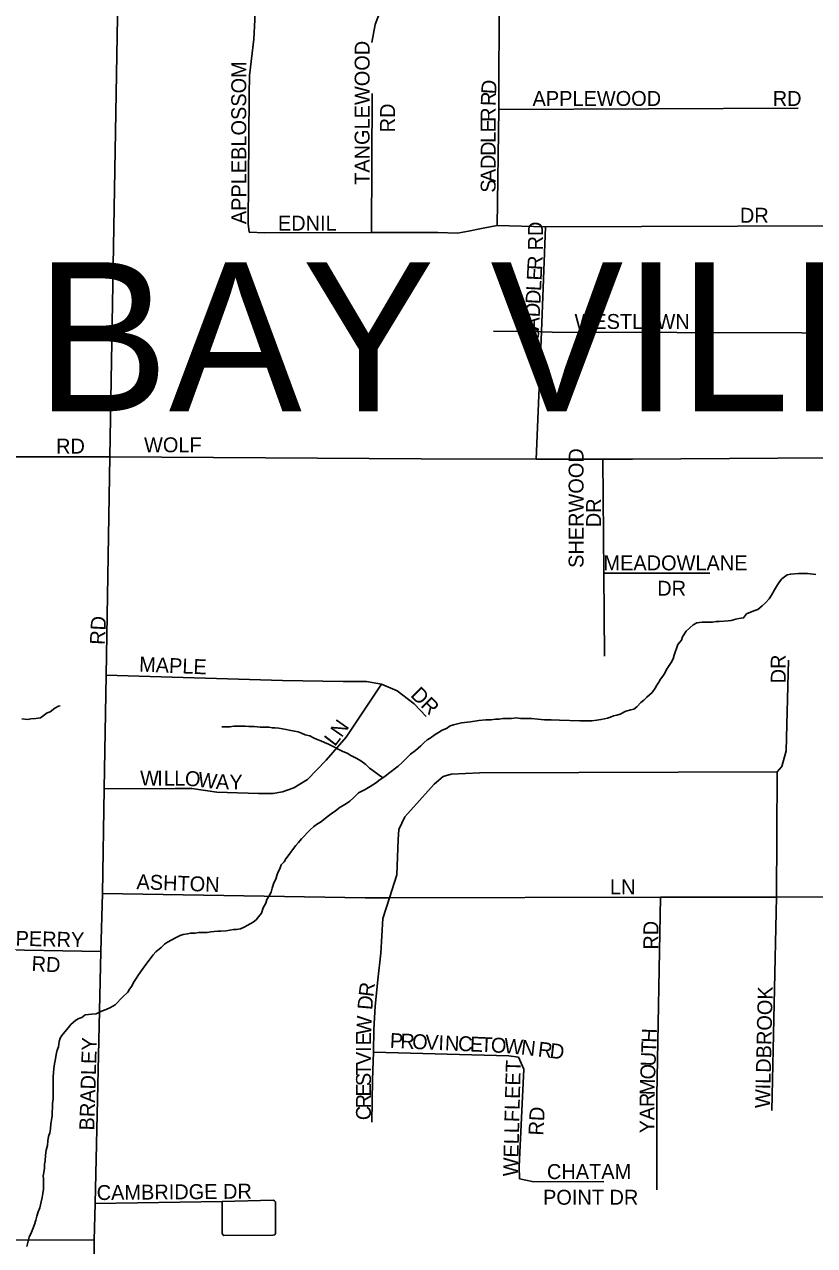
# Model space of a CAD drawing. Extents: x 2010165 to 2382125, y 1060529 to 1407316.
# Drawn here: x 2116231 to 2118880, y 1267507 to 1271602 of the extents above; entities that cross this region are included whole.
import ezdxf

# ---------------------------------------------------------------- set-up
doc = ezdxf.new("R2010")
doc.units = 0
for name, color, linetype in [('GM_X_City_Street', 7, 'Continuous'), ('GM_X_City_Street_Text', 7, 'Continuous'), ('GM_X_Corporation_Text', 7, 'Continuous'), ('GM_X_Minor_River', 7, 'Continuous')]:
    doc.layers.add(name, color=color, linetype=linetype)

msp = doc.modelspace()

# ---------------------------------------------------------------- linework, layer by layer
at = {"layer": 'GM_X_City_Street'}
for points in [[(2116464.5, 1267467), (2116465.1, 1267525), (2116467.9, 1267647.2), (2116487.6, 1268493.4), (2116492.2, 1268687.3), (2116498.1, 1269038.7), (2116504.5, 1269419.7), (2116516.9, 1270152.2), (2116550.8, 1272077), (2116556.8, 1272422.1), (2116559, 1272542.9), (2116566.7, 1272843.5), (2116570.2, 1273148.5), (2116574.6, 1273527.5), (2116584.4, 1274380.4), (2116589.8, 1274845.8)], [(2116984.6, 1270905.5), (2116980.7, 1270933.5), (2116984.7, 1271366.6), (2116985, 1271430.7), (2116999.5, 1271553), (2117003.8, 1271617.1), (2117007.3, 1271755.5), (2117011.2, 1271907.8), (2117013.4, 1271949.9), (2117023.5, 1271985.9), (2117043.7, 1272025.9), (2117070.1, 1272100), (2117090.3, 1272146), (2117097.6, 1272173.4), (2117110.7, 1272222.1), (2117125, 1272294.2), (2117135.6, 1272412.5), (2117147.1, 1272741.3)], [(2117395.9, 1271541.3), (2117406.2, 1271601.4), (2117436.5, 1271681.5), (2117453.8, 1271719), (2117499.2, 1271817.6), (2117531.6, 1271897.6), (2117554.1, 1271989.7), (2117557.2, 1272021.7), (2117581.4, 1272272.3), (2117603.6, 1272739.6)], [(2117815.5, 1270928.1), (2117821, 1271317.1), (2117821.4, 1271347.1), (2117822.9, 1271679.9)], [(2117394.9, 1270904.2), (2117397.1, 1271370.9)], [(2117821, 1271317.1), (2118824.3, 1271320.9)], [(2116984.6, 1270905.5), (2117036.6, 1270903.2), (2117394.9, 1270904.2), (2117617.2, 1270904.9), (2117683.2, 1270902.6), (2117719.3, 1270908.4), (2117763.4, 1270918.3), (2117815.5, 1270928.1), (2117977.6, 1270923.4), (2119264.7, 1270928)], [(2117946.1, 1270144.6), (2117963.9, 1270571), (2117964, 1270572.6), (2117977.6, 1270923.4)], [(2117803.9, 1270573.3), (2117963.9, 1270571), (2118000.1, 1270570.5), (2119255.1, 1270567.1)], [(2116516.9, 1270152.2), (2117561.4, 1270145.3), (2117946.1, 1270144.6), (2118170.3, 1270144.2), (2118269.7, 1270144.1), (2119244.1, 1270151.1), (2119848.3, 1270161.8), (2120170.4, 1270158.2), (2120248.4, 1270170.3), (2120330.4, 1270228.5), (2120476.4, 1270308.7), (2120580.4, 1270361), (2120672.5, 1270395.1), (2120792, 1270390.5), (2120970.6, 1270369.4)], [(2115138.1, 1270150.7), (2115580.8, 1270151.2), (2116011.9, 1270151.6), (2116516.9, 1270152.2)], [(2118175.3, 1269483.1), (2118173.2, 1269761.7), (2118170.3, 1270144.2)], [(2118173.2, 1269761.7), (2118528.9, 1269762.3)], [(2118736.9, 1267959.1), (2118752.2, 1268675.7), (2118754.1, 1269095.8), (2118770.2, 1269113.8), (2118784.4, 1269165.8), (2118791.9, 1269470.5)], [(2116498.1, 1269038.7), (2116735.8, 1269039.9), (2116791.9, 1269039.7), (2116875.9, 1269027.3), (2117016, 1269022.8), (2117064.1, 1269022.5), (2117096.2, 1269028.4), (2117134.2, 1269042.3), (2117180.4, 1269070.2), (2117242.8, 1269134.1), (2117309.2, 1269212), (2117428.1, 1269389.9)], [(2116504.5, 1269419.7), (2117095.8, 1269401.3), (2117300, 1269398.5), (2117378.1, 1269398.2), (2117428.1, 1269389.9), (2117480.1, 1269367.7), (2117537.9, 1269323.3), (2117577.8, 1269281.1)], [(2117395.4, 1267920.5), (2117398.1, 1268062.9), (2117400.7, 1268155.2), (2117402.8, 1268231.2), (2117407.2, 1268309.4), (2117415.6, 1268397.6), (2117426, 1268487.8), (2117432.5, 1268604), (2117454.5, 1268672.6), (2117479.3, 1268750.2), (2117483.8, 1268868.4), (2117486, 1268902.5), (2117506.2, 1268944.5), (2117604.8, 1269054.4), (2117634.9, 1269080.3), (2117661, 1269088.2), (2117757.1, 1269091.9), (2118754.1, 1269095.8)], [(2116492.2, 1268687.3), (2117372.8, 1268672.4), (2117454.5, 1268672.6), (2118363.7, 1268674.8), (2118752.2, 1268675.7), (2119215.2, 1268676.8)], [(2118351.3, 1267694), (2118350.8, 1268008.8), (2118363.7, 1268674.8)], [(2116102.8, 1268499.2), (2116487.6, 1268493.4)], [(2117400.7, 1268155.2), (2117854.9, 1268143.2), (2117886.9, 1268139)], [(2117891, 1267730), (2117889.2, 1267772.1), (2117904.7, 1268098.8), (2117886.9, 1268139)], [(2117891, 1267730), (2117933, 1267721.8), (2118173.3, 1267720.8)], [(2116467.9, 1267647.2), (2116894, 1267654.4)], [(2116894, 1267654.4), (2116894, 1267547.7), (2116896.5, 1267542.7), (2116899.9, 1267540.1), (2117064.2, 1267541.7), (2117069.9, 1267543.2), (2117072.4, 1267547.6), (2117072.1, 1267652.9), (2117069.6, 1267657), (2117064.9, 1267658.8), (2116894, 1267654.4)], [(2113971.4, 1267533.5), (2116465.1, 1267525)]]:
    msp.add_lwpolyline(points, dxfattribs=at)
at = {"layer": 'GM_X_Minor_River'}
for points in [[(2117796.1, 1269269.8), (2117810.1, 1269271.8), (2117822.2, 1269271.9), (2117834.2, 1269273.9), (2117848.2, 1269273.9), (2117864.3, 1269274), (2117880.3, 1269276.1), (2117894.4, 1269274.1), (2117912.5, 1269274.2), (2117930.5, 1269274.2), (2117952.6, 1269272.3), (2117974.7, 1269270.3), (2117996.8, 1269270.4), (2118024.9, 1269268.5), (2118093.1, 1269266.7), (2118113.2, 1269266.8), (2118133.2, 1269266.8), (2118149.3, 1269268.9), (2118163.3, 1269270.9), (2118175.3, 1269273), (2118185.4, 1269275), (2118195.4, 1269279.1), (2118205.4, 1269283.1), (2118217.4, 1269285.2), (2118227.5, 1269289.2), (2118247.5, 1269299.3), (2118263.5, 1269303.4), (2118273.6, 1269305.4), (2118283.6, 1269313.5), (2118297.6, 1269327.6), (2118307.6, 1269335.6), (2118317.6, 1269345.7), (2118335.6, 1269361.8), (2118345.6, 1269375.9), (2118351.5, 1269385.9), (2118357.5, 1269396), (2118363.5, 1269406), (2118371.5, 1269416.1), (2118377.5, 1269426.1), (2118383.5, 1269438.2), (2118399.4, 1269462.3), (2118405.4, 1269474.4), (2118409.4, 1269486.4), (2118421.3, 1269522.6), (2118433.3, 1269536.7), (2118437.3, 1269548.7), (2118449.2, 1269566.8), (2118473.2, 1269589), (2118485.3, 1269595), (2118503.3, 1269597.1), (2118525.4, 1269597.2), (2118537.4, 1269597.2), (2118549.5, 1269599.2), (2118559.5, 1269599.3), (2118589.6, 1269601.4), (2118599.6, 1269603.4), (2118615.7, 1269607.5), (2118625.7, 1269609.5), (2118641.7, 1269611.6), (2118651.7, 1269625.7), (2118675.8, 1269635.8), (2118689.8, 1269639.8), (2118703.8, 1269651.9), (2118715.8, 1269662), (2118727.8, 1269676.1), (2118735.8, 1269688.1), (2118745.8, 1269706.2), (2118755.7, 1269722.3), (2118761.7, 1269732.3), (2118769.7, 1269742.4), (2118787.7, 1269756.5), (2118799.8, 1269758.6), (2118825.8, 1269760.6), (2118843.9, 1269760.7), (2118855.9, 1269760.8), (2118884, 1269756.8)], [(2116222.8, 1269272.8), (2116240.9, 1269270.8), (2116252.9, 1269272.9), (2116268.9, 1269274.9), (2116285, 1269277), (2116307, 1269293.1), (2116317, 1269297.2), (2116333, 1269309.2), (2116345.1, 1269315.3), (2116351.1, 1269317.3)], [(2116519.1, 1268304.6), (2116535.2, 1268314.6), (2116561.2, 1268340.8), (2116577.1, 1268356.9), (2116583.1, 1268367), (2116591.1, 1268377), (2116597.1, 1268389.1), (2116603.1, 1268399.1), (2116613.1, 1268415.2), (2116627, 1268433.3), (2116641, 1268453.4), (2116649, 1268463.5), (2116663, 1268481.6), (2116671, 1268491.6), (2116689, 1268505.8), (2116701, 1268517.8), (2116711, 1268523.9), (2116725, 1268532), (2116739.1, 1268540), (2116753.1, 1268546.1), (2116763.1, 1268550.1), (2116777.1, 1268552.2), (2116787.2, 1268554.2), (2116803.2, 1268554.3), (2116815.3, 1268556.3), (2116829.3, 1268556.4), (2116843.4, 1268556.4), (2116855.4, 1268558.5), (2116867.4, 1268560.5), (2116879.5, 1268560.6), (2116889.5, 1268560.6), (2116907.5, 1268562.6), (2116919.6, 1268564.7), (2116931.6, 1268566.7), (2116941.6, 1268566.8), (2116955.7, 1268568.8), (2116967.7, 1268574.9), (2116997.7, 1268591), (2117007.8, 1268599.1), (2117015.7, 1268609.1), (2117025.7, 1268621.2), (2117031.7, 1268639.3), (2117039.7, 1268655.4), (2117043.6, 1268667.4), (2117051.6, 1268679.5), (2117057.6, 1268691.5), (2117061.6, 1268705.6), (2117067.5, 1268723.7), (2117073.5, 1268735.7), (2117077.5, 1268747.8), (2117081.4, 1268759.8), (2117087.4, 1268769.9), (2117091.4, 1268783.9), (2117101.4, 1268794), (2117107.4, 1268804.1), (2117115.4, 1268814.1), (2117129.3, 1268834.2), (2117141.3, 1268848.3), (2117149.3, 1268858.4), (2117159.3, 1268870.4), (2117169.3, 1268880.5), (2117179.3, 1268890.6), (2117189.3, 1268900.6), (2117201.3, 1268912.7), (2117213.3, 1268920.8), (2117223.3, 1268926.8), (2117233.4, 1268934.9), (2117245.4, 1268945), (2117259.4, 1268955), (2117273.4, 1268965.1), (2117289.4, 1268977.2), (2117307.4, 1268987.3), (2117321.4, 1268997.4), (2117335.4, 1269009.5), (2117351.4, 1269025.6), (2117373.5, 1269035.7), (2117389.5, 1269045.8), (2117407.5, 1269057.8), (2117423.5, 1269069.9), (2117439.5, 1269080), (2117451.5, 1269090.1), (2117483.6, 1269114.3), (2117497.6, 1269126.4), (2117507.6, 1269136.4), (2117525.6, 1269154.5), (2117541.6, 1269166.6), (2117559.6, 1269182.8), (2117569.6, 1269192.8), (2117581.6, 1269202.9), (2117591.6, 1269208.9), (2117607.6, 1269221), (2117619.6, 1269227.1), (2117631.7, 1269235.1), (2117645.7, 1269241.2), (2117657.7, 1269249.3), (2117669.7, 1269253.3), (2117695.8, 1269259.4), (2117725.9, 1269263.5), (2117754, 1269267.6), (2117778, 1269269.7), (2117796.1, 1269269.8)], [(2117431.9, 1269075.2), (2117399.3, 1269100), (2117387.3, 1269107.9), (2117375.2, 1269119.9), (2117359.1, 1269131.9), (2117345, 1269139.9), (2117324.9, 1269149.9), (2117312.8, 1269157.9), (2117298.8, 1269163.8), (2117282.7, 1269171.8), (2117268.6, 1269179.8), (2117250.5, 1269187.8), (2117236.5, 1269193.8), (2117224.4, 1269199.7), (2117212.4, 1269203.7), (2117200.3, 1269209.7), (2117188.2, 1269215.7), (2117172.2, 1269219.6), (2117160.1, 1269225.6), (2117148.1, 1269229.6), (2117136, 1269231.6), (2117117.9, 1269235.5), (2117107.9, 1269237.5), (2117095.8, 1269239.4), (2117083.8, 1269241.4), (2117071.7, 1269243.4), (2117061.7, 1269243.4), (2117051.7, 1269245.3), (2117041.6, 1269245.3), (2117021.6, 1269245.2), (2117001.5, 1269247.2), (2116983.4, 1269247.1), (2116971.4, 1269249.1), (2116959.4, 1269249.1), (2116945.3, 1269249), (2116933.3, 1269249), (2116919.2, 1269246.9), (2116907.2, 1269246.9), (2116897.1, 1269246.8), (2116893.1, 1269246.8)], [(2116239, 1267503.1), (2116242.9, 1267517.1), (2116246.9, 1267535.2), (2116254.9, 1267551.2), (2116258.8, 1267563.3), (2116264.8, 1267577.4), (2116268.8, 1267591.4), (2116272.7, 1267605.5), (2116276.7, 1267619.5), (2116282.7, 1267633.6), (2116286.6, 1267653.7), (2116290.6, 1267667.8), (2116292.5, 1267681.8), (2116294.5, 1267695.8), (2116294.4, 1267707.9), (2116294.4, 1267719.9), (2116294.4, 1267730), (2116294.3, 1267740), (2116296.3, 1267752.1), (2116298.3, 1267766.1), (2116298.2, 1267780.1), (2116300.2, 1267790.2), (2116302.1, 1267810.2), (2116304.1, 1267826.3), (2116308, 1267842.4), (2116310, 1267858.4), (2116311.9, 1267872.5), (2116315.9, 1267884.5), (2116317.9, 1267898.6), (2116319.8, 1267914.6), (2116321.8, 1267928.7), (2116323.7, 1267940.8), (2116323.7, 1267954.8), (2116325.6, 1267968.8), (2116325.6, 1267982.9), (2116327.5, 1267998.9), (2116327.5, 1268011), (2116327.5, 1268023), (2116327.4, 1268035.1), (2116327.4, 1268047.1), (2116327.3, 1268057.1), (2116327.3, 1268073.2), (2116329.2, 1268099.3), (2116331.2, 1268109.3), (2116333.1, 1268121.4), (2116335.1, 1268133.4), (2116337.1, 1268147.5), (2116341, 1268161.5), (2116345, 1268173.6), (2116346.9, 1268191.6), (2116350.9, 1268201.7), (2116356.9, 1268211.7), (2116366.9, 1268223.8), (2116378.9, 1268237.9), (2116386.9, 1268247.9), (2116402.9, 1268262.1), (2116412.9, 1268268.1), (2116422.9, 1268272.1), (2116434.9, 1268280.2), (2116457, 1268282.3), (2116471, 1268284.3), (2116489.1, 1268292.4), (2116505.1, 1268298.5), (2116519.1, 1268304.6)]]:
    msp.add_lwpolyline(points, dxfattribs=at)

# ---------------------------------------------------------------- texts
at = {"layer": 'GM_X_City_Street_Text'}
for s, rotation, p in [('TANGLEWOOD', 90, (2117388.1, 1271064.3)), ('APPLEBLOSSOM', 90, (2116974.5, 1270932.3)), ('D', 86.7195, (2117811.8, 1271367.1)), ('R', 88.1904, (2117810.6, 1271327.9)), ('APPLEWOOD', 0, (2117934.3, 1271328.9)), ('RD', 0, (2118739.5, 1271328.9)), ('RD', 90, (2117473.2, 1271240.3)), ('R', 89.9757, (2117810.6, 1271275.5)), ('E', 89.9863, (2117810.6, 1271240.3)), ('L', 89.9863, (2117810.6, 1271205.1)), ('D', 89.987, (2117810.6, 1271161.1)), ('D', 89.9781, (2117810.6, 1271117.1)), ('A', 89.987, (2117810.5, 1271073.1)), ('S', 89.9863, (2117810.5, 1271037.9)), ('DR', 0, (2118629.5, 1270937.1)), ('EDNIL', 0, (2117080.7, 1270910.7)), ('RD', 90, (2117969, 1270844.3)), ('R', 87.0405, (2117966.4, 1270777.3)), ('E', 87.0375, (2117964.6, 1270742.2)), ('L', 87.0429, (2117962.7, 1270707.1)), ('D', 87.0431, (2117960.5, 1270663.1)), ('D', 87.0372, (2117958.2, 1270619.2)), ('A', 87.3766, (2117956.2, 1270575.3)), ('WESTLAWN', 0, (2118075.1, 1270580.9)), ('S', 89.2487, (2117955.7, 1270540.5)), ('RD', 0, (2116337.1, 1270162.9)), ('WOLF', 0, (2116632, 1270167.3)), ('SHERWOOD', 90, (2118105.3, 1269779.5)), ('DR', 90, (2118164, 1269915.9)), ('MEADOWLANE', 0, (2118172, 1269771.3)), ('DR', 0, (2118352.3, 1269686.2)), ('RD', 86.9884, (2116500, 1269520.4)), ('MAPLE', 357.56, (2116614.7, 1269431.9)), ('DR', 90, (2118783, 1269392.3)), ('DR', 314.9961, (2117522.6, 1269350.1)), ('N', 54.8915, (2117294.2, 1269207.9)), ('L', 52.4197, (2117271.4, 1269178.1)), ('W', 359.9328, (2116618.7, 1269049.7)), ('I', 359.9126, (2116675.9, 1269049.6)), ('L', 359.939, (2116698, 1269049.6)), ('L', 359.918, (2116733.2, 1269049.6)), ('O', 355.3171, (2116767.3, 1269049.6)), ('W', 352.6153, (2116810.5, 1269046)), ('A', 357.7635, (2116872.1, 1269038.3)), ('Y', 359.9929, (2116918.2, 1269036.5)), ('ASHTON', 357.9518, (2116605.9, 1268702.1)), ('LN', 0, (2118193.9, 1268684.5)), ('RD', 90, (2118356.1, 1268499.1)), ('PERRY', 358.7276, (2116200.9, 1268512.3)), ('RD', 356.989, (2116254, 1268427.9)), ('R', 83.0376, (2117400.6, 1268338.9)), ('WILDBROOK', 88.6528, (2118730.1, 1267966.9)), ('D', 85.0875, (2117396.9, 1268295.6)), ('W', 86.5768, (2117392.6, 1268212.3)), ('BRADLEY', 88.2636, (2116464.8, 1267892.2)), ('E', 89.9727, (2117392.6, 1268177.9)), ('P', 357.4582, (2117455.2, 1268169.7)), ('R', 357.4867, (2117490.4, 1268168.1)), ('O', 357.4639, (2117529.9, 1268166.4)), ('V', 357.4933, (2117573.9, 1268164.4)), ('I', 357.4639, (2117617.8, 1268162.5)), ('N', 357.4708, (2117639.8, 1268161.5)), ('C', 357.4804, (2117683.8, 1268159.6)), ('E', 357.4582, (2117723.4, 1268157.9)), ('T', 357.4908, (2117758.5, 1268156.3)), ('O', 357.4639, (2117793.7, 1268154.7)), ('W', 354.798, (2117837, 1268152.8)), ('H', 87.7915, (2118349.7, 1268186.1)), ('I', 89.9781, (2117392.6, 1268155.9)), ('N', 353.3847, (2117893.7, 1268147.7)), ('R', 353.3554, (2117950.5, 1268141.1)), ('D', 353.3732, (2117989.9, 1268136.5)), ('T', 87.8005, (2118348.3, 1268150.9)), ('V', 89.9703, (2117392.6, 1268111.9)), ('WELLFLEET', 88.5674, (2117885.4, 1267738.1)), ('U', 87.7973, (2118346.6, 1268106.9)), ('S', 89.9707, (2117392.6, 1268041.5)), ('T', 89.9764, (2117392.6, 1268076.7)), ('O', 87.7915, (2118344.9, 1268062.9)), ('E', 89.9764, (2117392.6, 1268006.3)), ('M', 88.1418, (2118343.2, 1268010.3)), ('R', 89.9703, (2117392.6, 1267966.7)), ('R', 89.6478, (2118343, 1267971)), ('C', 89.9757, (2117392.5, 1267927.1)), ('RD', 86.9833, (2117970.3, 1267874.7)), ('A', 89.9672, (2118342.9, 1267927.1)), ('Y', 89.9781, (2118342.9, 1267883.1)), ('CHATAM', 0, (2117982.7, 1267729.7)), ('CAMBRIDGE DR', 0.5402, (2116473.5, 1267659.3)), ('POINT DR', 0, (2117969.5, 1267643.7))]:
    msp.add_text(s, height=50, rotation=rotation, dxfattribs=at).set_placement(p)
at = {"layer": 'GM_X_Corporation_Text'}
msp.add_text('BAY VILLAGE', height=500, rotation=0, dxfattribs=at).set_placement((2116269, 1270304.6))

doc.saveas('drawing.dxf')
